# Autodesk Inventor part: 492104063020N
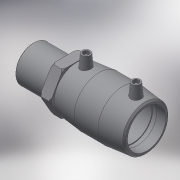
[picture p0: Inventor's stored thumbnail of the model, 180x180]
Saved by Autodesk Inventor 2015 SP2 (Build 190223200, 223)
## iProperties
Created: 2017-06
Part Number: 492104063020N
Material: Generic
Description: PLASSON Male Transition Coupler 63 x 2"
Document SubType Name: Modeling
Designer: KIM
Mass: 394.797 g
Surface Area: 871.381 cm^2
Volume: 394.797 cm^3
Density: 1 g/cm^3
Appearance: Default
Author: KIM
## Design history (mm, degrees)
derived "492104.ipt"
feature "Solid1::492104.ipt"
tag "TaggingFeature1"
body "Solid1"
other parameters: "d0" = 117, "d1" = 63, "d2" = 82, "d3" = 57, "d4" = 39, "d5" = 73.8, "d6" = 59.85, "d7" = 63, "d8" = 168 deg, "d10" = 22.8, "d11" = 7.6, "d29" = 58, "d30" = 14, "d31" = 40.95, "d34" = 5 deg, "d41" = 4, "d42" = 14, "d43" = 0, "d48" = 3, "d49" = 0, "d57" = 47, "d58" = 59.614, "d59" = 47.6912, "d60" = 62.1, "d61" = 82, "d62" = 1.19228, "d65" = 2.46, "d70" = 0.1, "d71" = 69, "d72" = 17.25, "d73" = 22.8, "d75" = 0, "d_" = 63, "L_" = 186, "L_1" = 57, "D_1" = 82, "A_" = 58, "d_2" = 12, "L_2" = 69, "D_" = 47, "R_" = 59.614
